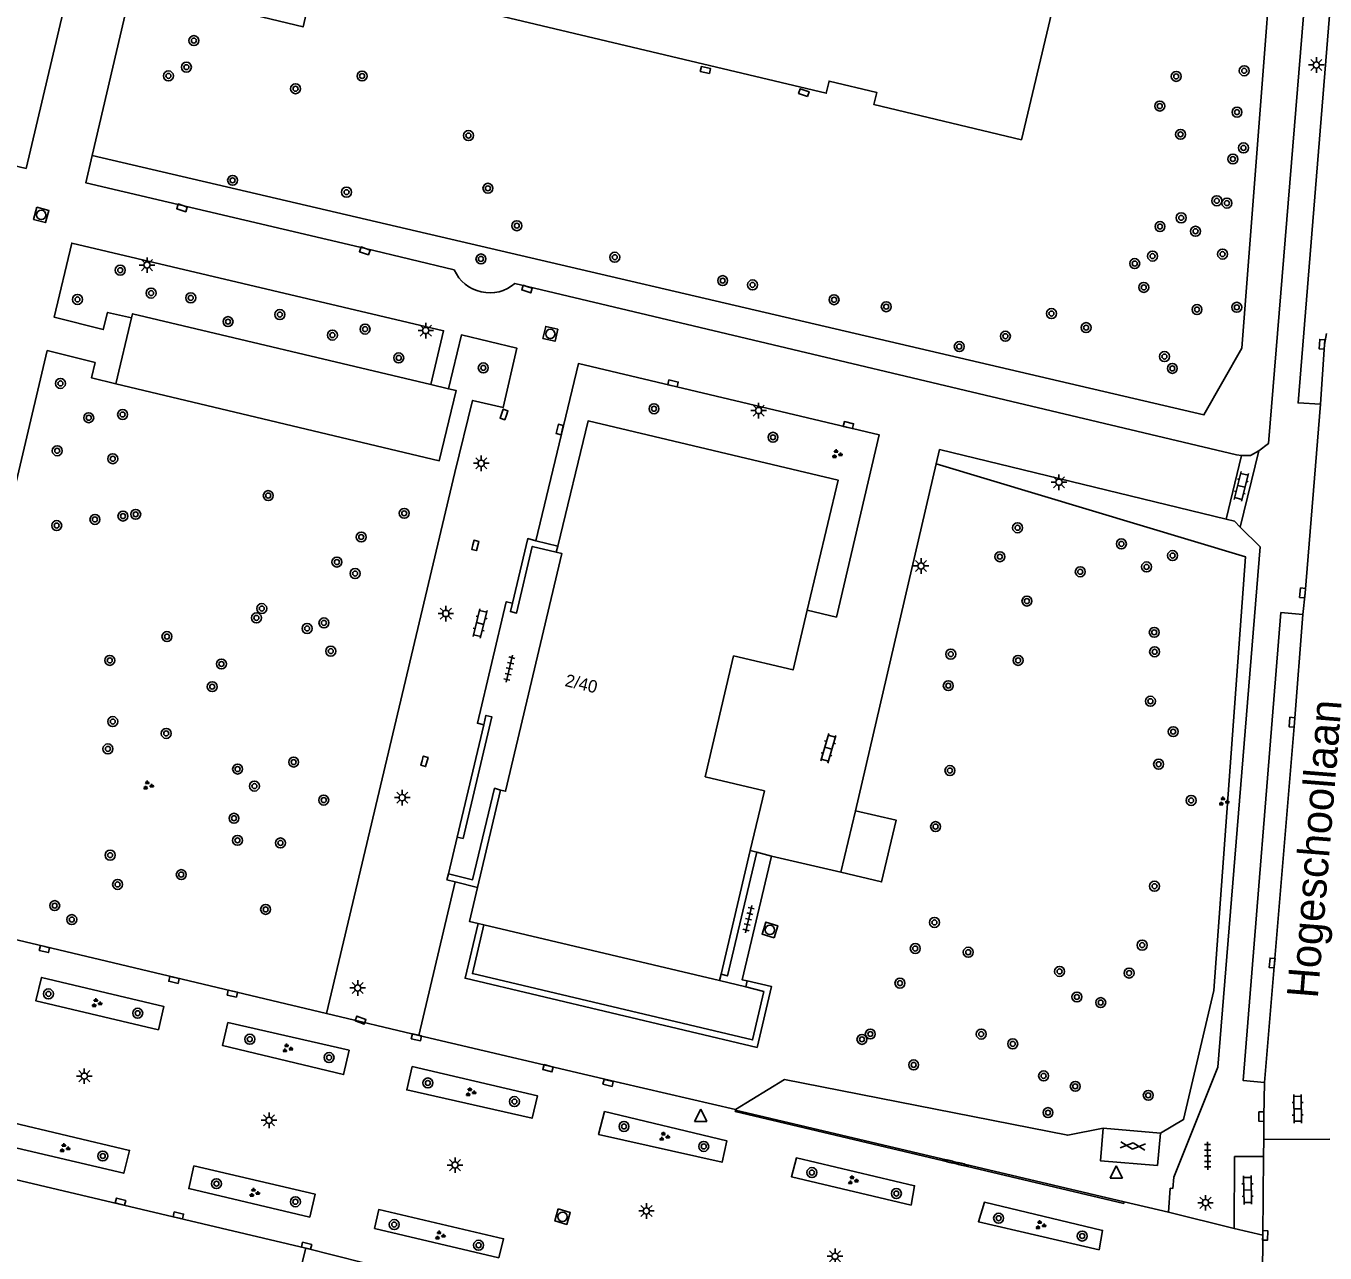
# Model space of a CAD drawing. Extents: x 131000 to 133014, y 396499 to 399001.
# Drawn here: x 131216.5 to 131320.7, y 397191 to 397289.5 of the extents above; entities that cross this region are included whole.
import ezdxf

# ---------------------------------------------------------------- set-up
doc = ezdxf.new("R2010")
doc.units = 0
for name, color, linetype in [('gg-afsc-muur', 7, 'Continuous'), ('gg-anno-huisnummerreeks BGT', 7, 'Continuous'), ('gg-anno-openbare ruimte label', 7, 'Continuous'), ('gg-bbg-bijgebouw', 7, 'Continuous'), ('gg-bbg-gedigitaliseerde bijgebouw', 7, 'Continuous'), ('gg-bbg-hoofdgebouw', 7, 'Continuous'), ('gg-knt-verharding', 7, 'Continuous'), ('gg-knt-verharding nz', 7, 'Continuous'), ('gt-grn-afwateringsgoot', 7, 'Continuous'), ('gt-grn-groengrens', 7, 'Continuous'), ('gt-grn-weggrens', 7, 'Continuous'), ('gt-symb-afwateringsgoot', 7, 'Continuous'), ('gt-symb-boom', 7, 'Continuous'), ('gt-symb-gesloten verharding', 7, 'Continuous'), ('gt-symb-groenvak', 7, 'Continuous'), ('gt-symb-klinker verharding', 7, 'Continuous'), ('gt-symb-kolk', 7, 'Continuous'), ('gt-symb-kolk center center', 7, 'Continuous'), ('gt-symb-lichtmast', 7, 'Continuous'), ('gt-symb-rioolschacht', 7, 'Continuous'), ('gt-symb-tegel verharding', 7, 'Continuous'), ('gt-symb-waterafsluiter', 7, 'Continuous')]:
    doc.layers.add(name, color=color, linetype=linetype)

# ---------------------------------------------------------------- blocks, each defined once
blk = doc.blocks.new('gt0-BOOM')
at = {"layer": 'gt-symb-boom'}
for radius in [0.4, 0.2]:
    blk.add_circle((0, 0), radius, dxfattribs=at)
blk = doc.blocks.new('gt0-KOLKCC')
at = {"layer": 'gt-symb-kolk center center'}
blk.add_lwpolyline([(-0.37, 0.2), (0.38, 0.2), (0.38, -0.2), (-0.37, -0.2)], close=True, dxfattribs=at)
blk = doc.blocks.new('gt0-LMAST')
at = {"layer": 'gt-symb-lichtmast'}
for p, q in [((-0.18, 0.17), (-0.45, 0.44)), ((-0.01, 0.25), (-0.01, 0.62)), ((0.17, 0.17), (0.44, 0.44)), ((-0.26, 0), (-0.63, 0)), ((-0.18, -0.18), (-0.45, -0.45)), ((-0.01, -0.25), (-0.01, -0.63)), ((0.44, -0.45), (0.17, -0.18)), ((0.24, 0), (0.62, 0))]:
    blk.add_line(p, q, dxfattribs=at)
blk.add_circle((-0.01, 0), 0.25, dxfattribs=at)
blk = doc.blocks.new('gt0-KOLK')
at = {"layer": 'gt-symb-kolk'}
blk.add_lwpolyline([(0, 0), (0.38, 0), (0.38, 0.4), (-0.38, 0.4), (-0.38, 0), (0, 0)], dxfattribs=at)
blk = doc.blocks.new('gt0-KL1')
at = {"layer": 'gt-symb-klinker verharding'}
for p, q in [((-1.15, 0.3), (1.15, 0.3)), ((-1, -0.3), (-1, 0.3)), ((-0.5, 0.3), (-0.5, 0.45)), ((0, -0.3), (0, 0.3)), ((0.5, 0.3), (0.5, 0.45)), ((1, -0.3), (1, 0.3)), ((-1.15, -0.3), (1.15, -0.3)), ((-0.5, -0.45), (-0.5, -0.3)), ((0.5, -0.45), (0.5, -0.3))]:
    blk.add_line(p, q, dxfattribs=at)
blk = doc.blocks.new('gt0-TEG1')
at = {"layer": 'gt-symb-tegel verharding'}
for p, q in [((-1.12, 0), (1.12, 0)), ((-0.9, -0.25), (-0.9, 0.25)), ((-0.45, -0.25), (-0.45, 0.25)), ((0, -0.25), (0, 0.25)), ((0.45, -0.25), (0.45, 0.25)), ((0.9, -0.25), (0.9, 0.25))]:
    blk.add_line(p, q, dxfattribs=at)
blk = doc.blocks.new('gt0-GRVAK')
at = {"layer": 'gt-symb-groenvak'}
for p, q in [((-0.11, 0.19), (-0.23, 0.24)), ((-0.18, 0.15), (0.09, 0.15)), ((-0.09, 0.21), (-0.16, 0.32)), ((-0.05, 0.21), (-0.05, 0.39)), ((0, 0.21), (0.06, 0.32)), ((0.02, 0.19), (0.13, 0.24)), ((0.26, -0.05), (0.2, 0.06)), ((0.3, -0.05), (0.3, 0.13)), ((0.35, -0.05), (0.41, 0.06)), ((-0.24, -0.23), (-0.36, -0.18)), ((-0.32, -0.26), (-0.05, -0.26)), ((-0.23, -0.21), (-0.29, -0.09)), ((-0.18, -0.2), (-0.18, -0.02)), ((-0.14, -0.21), (-0.07, -0.09)), ((-0.12, -0.23), (0, -0.18)), ((0.24, -0.07), (0.12, -0.02)), ((0.17, -0.11), (0.44, -0.11)), ((0.37, -0.07), (0.49, -0.02))]:
    blk.add_line(p, q, dxfattribs=at)
blk = doc.blocks.new('gt0-RS')
at = {"layer": 'gt-symb-rioolschacht'}
blk.add_lwpolyline([(-0.5, -0.5), (0.5, -0.5), (0.5, 0.5), (-0.5, 0.5)], close=True, dxfattribs=at)
blk.add_circle((0, 0), 0.375, dxfattribs=at)
blk = doc.blocks.new('gt0-GESVH1')
at = {"layer": 'gt-symb-gesloten verharding'}
for p, q in [((-0.99, -0.26), (0.01, 0.24)), ((0.01, -0.26), (-0.99, 0.24)), ((0.01, 0.24), (1.01, -0.26)), ((1.01, 0.24), (0.01, -0.26))]:
    blk.add_line(p, q, dxfattribs=at)
blk = doc.blocks.new('gt0-AFWGT_1')
at = {"layer": 'gt-symb-afwateringsgoot'}
for p, q in [((-1.08, 0), (-0.73, 0)), ((-0.23, 0), (0.22, 0)), ((0.72, 0), (1.07, 0))]:
    blk.add_line(p, q, dxfattribs=at)
for points in [[(-0.73, 0.08), (-0.23, 0.08), (-0.23, -0.08), (-0.73, -0.08)], [(0.22, 0.08), (0.72, 0.08), (0.72, -0.08), (0.22, -0.08)]]:
    blk.add_lwpolyline(points, close=True, dxfattribs=at)
blk = doc.blocks.new('gt0-WAFSL')
at = {"layer": 'gt-symb-waterafsluiter'}
for p, q in [((-0.5, -0.33), (0, 0.67)), ((0, 0.67), (0.5, -0.33)), ((0.5, -0.33), (-0.5, -0.33))]:
    blk.add_line(p, q, dxfattribs=at)

msp = doc.modelspace()

# ---------------------------------------------------------------- linework, layer by layer
at = {"layer": 'gg-afsc-muur'}
for p, q in [((131257.4, 397248.18), (131259.16, 397247.75)), ((131251.07, 397224.39), (131253.21, 397233.42)), ((131252.71, 397220.36), (131250.92, 397220.81)), ((131274.26, 397212.39), (131274.36, 397212.87))]:
    msp.add_line(p, q, dxfattribs=at)
for points in [[(131255.52, 397243.16), (131256.75, 397248.35), (131257.4, 397248.18)], [(131255.52, 397243.16), (131255.36, 397242.49), (131255.85, 397242.37), (131257.11, 397247.72), (131259.04, 397247.26)], [(131253.21, 397233.42), (131253.39, 397234.17), (131253.87, 397234.05), (131251.56, 397224.29), (131251.07, 397224.39)], [(131250.38, 397221.45), (131252.32, 397220.98), (131254.08, 397228.32), (131254.55, 397228.17)], [(131250.92, 397220.81), (131250.26, 397220.97), (131250.38, 397221.45)], [(131274.36, 397212.87), (131276.3, 397212.42), (131275.15, 397207.53), (131251.72, 397213.07), (131252.76, 397217.46)], [(131253.23, 397217.35), (131252.31, 397213.45), (131274.79, 397208.13), (131275.69, 397212.01), (131274.26, 397212.39)]]:
    msp.add_lwpolyline(points, dxfattribs=at)
at = {"layer": 'gg-bbg-bijgebouw'}
for p, q in [((131223.69, 397260.77), (131224.95, 397266.07)), ((131248.96, 397260.72), (131250.39, 397260.38))]:
    msp.add_line(p, q, dxfattribs=at)
for points in [[(131224.95, 397266.07), (131225.03, 397266.4), (131248.96, 397260.72)], [(131250.39, 397260.38), (131250.99, 397260.24), (131249.65, 397254.6), (131223.69, 397260.77)]]:
    msp.add_lwpolyline(points, dxfattribs=at)
at = {"layer": 'gg-bbg-gedigitaliseerde bijgebouw'}
msp.add_line((131283.04, 397226.52), (131281.88, 397221.58), dxfattribs=at)
msp.add_lwpolyline([(131281.88, 397221.58), (131285.15, 397220.81), (131286.32, 397225.75), (131283.04, 397226.52)], dxfattribs=at)
at = {"layer": 'gg-bbg-hoofdgebouw'}
for p, q in [((131259.16, 397247.75), (131259.04, 397247.26)), ((131254.55, 397228.17), (131252.71, 397220.36)), ((131274.61, 397223.32), (131272.27, 397213.4)), ((131252.76, 397217.46), (131253.23, 397217.35)), ((131253.23, 397217.35), (131272.14, 397212.88)), ((131272.27, 397213.4), (131272.14, 397212.88))]:
    msp.add_line(p, q, dxfattribs=at)
for points in [[(131239.74, 397293.82), (131280.7, 397284.09), (131280.93, 397285.06), (131284.76, 397284.16), (131284.52, 397283.19), (131296.37, 397280.36), (131299.28, 397292.64), (131300.25, 397292.41), (131309.51, 397331.52), (131308.54, 397331.75), (131310.56, 397340.26)], [(131279.18, 397242.61), (131281.65, 397253.05), (131261.59, 397257.79), (131259.16, 397247.75)], [(131259.04, 397247.26), (131259.47, 397247.16), (131254.97, 397228.08), (131254.55, 397228.17)], [(131279.18, 397242.61), (131278.04, 397237.82), (131273.26, 397238.94), (131270.99, 397229.24), (131275.74, 397228.11), (131274.61, 397223.32)], [(131252.71, 397220.36), (131252.06, 397217.63), (131252.76, 397217.46)]]:
    msp.add_lwpolyline(points, dxfattribs=at)
at = {"layer": 'gg-knt-verharding'}
for p, q in [((131207.38, 397218.12), (131218.18, 397263.44)), ((131289.52, 397254.36), (131289.78, 397255.51)), ((131312.79, 397249.91), (131289.78, 397255.51)), ((131312.79, 397249.91), (131314.03, 397255.03)), ((131315.41, 397255.39), (131313.93, 397249.26)), ((131240.6, 397210.25), (131250.9, 397253.65)), ((131283.04, 397226.52), (131289.52, 397254.36)), ((131250.38, 397221.45), (131251.07, 397224.39)), ((131275.13, 397223.2), (131274.61, 397223.32)), ((131275.13, 397223.2), (131276.3, 397222.88)), ((131276.3, 397222.88), (131281.88, 397221.58)), ((131248.01, 397208.49), (131250.92, 397220.81)), ((131240.6, 397210.25), (131207.38, 397218.12)), ((131272.14, 397212.88), (131274.26, 397212.39)), ((131273.43, 397202.49), (131273.43, 397202.53)), ((131307.54, 397200.65), (131302.92, 397201.04)), ((131307.3, 397198.05), (131307.54, 397200.65)), ((131315.8, 397198.78), (131315.81, 397200.14)), ((131315.81, 397200.14), (131321.11, 397200.15)), ((131315.73, 397192.47), (131315.8, 397198.78)), ((131212.81, 397197.59), (131238.94, 397191.41)), ((131308.16, 397194.31), (131308.31, 397196.23)), ((131304.61, 397195.12), (131308.16, 397194.31)), ((131313.44, 397193), (131308.16, 397194.31)), ((131254.43, 397190.63), (131244.45, 397193)), ((131238.31, 397188.97), (131238.94, 397191.41)), ((131238.94, 397191.41), (131243.58, 397190.25))]:
    msp.add_line(p, q, dxfattribs=at)
for points in [[(131143.37, 397295.53), (131153.22, 397293.21), (131172.1, 397288.66), (131216.48, 397278.05), (131227.1, 397323.04), (131154.21, 397340.33), (131143.37, 397295.53)], [(131319.61, 397297.84), (131316.19, 397255.97), (131315.41, 397255.39)], [(131320.36, 397259.14), (131318.57, 397259.24), (131321.67, 397297.63)], [(131239.74, 397293.82), (131238.72, 397289.41), (131225, 397292.72), (131224.62, 397291.22), (131221.78, 397279.09)], [(131221.78, 397279.09), (131221.27, 397276.91), (131243.73, 397271.63), (131250.85, 397269.92)], [(131248.96, 397260.72), (131249.99, 397265.03), (131220.15, 397272.07), (131218.74, 397266.11), (131222.67, 397265.13), (131223.03, 397266.5), (131224.95, 397266.07)], [(131255.71, 397268.82), (131313.64, 397255.07), (131314.03, 397255.03)], [(131250.9, 397253.65), (131252.32, 397259.44), (131254.78, 397258.88), (131255.87, 397263.64), (131251.42, 397264.69), (131250.39, 397260.38)], [(131223.69, 397260.77), (131221.73, 397261.26), (131222.02, 397262.47), (131218.18, 397263.44)], [(131279.18, 397242.61), (131281.52, 397242.05), (131284.94, 397256.68), (131260.81, 397262.4), (131257.4, 397248.18)], [(131320.36, 397259.14), (131319.13, 397243.97), (131318.95, 397242.27)], [(131314.03, 397255.03), (131314.76, 397255.02), (131315.41, 397255.39)], [(131308.31, 397196.23), (131308.51, 397196.21), (131308.59, 397197.11), (131312.12, 397205.95), (131315.52, 397247.7), (131313.93, 397249.26)], [(131313.93, 397249.26), (131313.46, 397249.75), (131312.79, 397249.91)], [(131255.52, 397243.16), (131255.02, 397243.29), (131252.71, 397233.54), (131253.21, 397233.42)], [(131315.89, 397204.71), (131314.17, 397204.86), (131317.2, 397242.41), (131318.95, 397242.27)], [(131272.27, 397213.4), (131272.77, 397213.26), (131275.13, 397223.2)], [(131276.3, 397222.88), (131273.95, 397212.96), (131274.36, 397212.87)], [(131227.11, 397208.93), (131227.55, 397210.8), (131217.73, 397213.14), (131217.26, 397211.27), (131227.11, 397208.93)], [(131232.67, 397209.53), (131232.24, 397207.68), (131241.97, 397205.35), (131242.4, 397207.3), (131232.67, 397209.53)], [(131273.43, 397202.53), (131264.19, 397204.68), (131248.01, 397208.49)], [(131247.48, 397205.98), (131247.04, 397204.11), (131257.1, 397201.84), (131257.52, 397203.65), (131247.48, 397205.98)], [(131315.89, 397204.71), (131315.83, 397201.97), (131315.81, 397200.14)], [(131262.9, 397202.37), (131262.43, 397200.54), (131272.34, 397198.31), (131272.73, 397200.02), (131262.9, 397202.37)], [(131214.89, 397201.61), (131214.41, 397199.76), (131224.32, 397197.43), (131224.79, 397199.26), (131214.89, 397201.61)], [(131302.92, 397201.04), (131302.71, 397198.43), (131307.3, 397198.05)], [(131287.51, 397194.86), (131287.79, 397196.42), (131278.31, 397198.66), (131277.91, 397197.14), (131287.51, 397194.86)], [(131313.44, 397193), (131313.48, 397198.76), (131315.8, 397198.78)], [(131229.95, 397198.03), (131229.54, 397196.2), (131239.25, 397193.91), (131239.68, 397195.75), (131229.95, 397198.03)], [(131302.62, 397191.29), (131302.88, 397192.84), (131293.4, 397195.1), (131292.91, 397193.54), (131302.62, 397191.29)], [(131254.43, 397190.63), (131254.81, 397192.17), (131244.79, 397194.51), (131244.45, 397193)], [(131315.73, 397192.47), (131315.69, 397185.77), (131315.55, 397173.32)]]:
    msp.add_lwpolyline(points, dxfattribs=at)
msp.add_arc((131253.69, 397271.18), 3.11, 204.0378, 310.6328, dxfattribs=at)
at = {"layer": 'gg-knt-verharding nz'}
msp.add_line((131315.73, 397192.47), (131313.44, 397193), dxfattribs=at)
for points in [[(131320.84, 397264.82), (131320.69, 397263.93), (131320.36, 397259.14)], [(131318.95, 397242.27), (131318.28, 397233.6), (131315.89, 397204.71)]]:
    msp.add_lwpolyline(points, dxfattribs=at)
at = {"layer": 'gt-grn-afwateringsgoot'}
msp.add_line((131304.61, 397195.12), (131273.43, 397202.49), dxfattribs=at)
msp.add_lwpolyline([(131273.43, 397202.49), (131273.4, 397202.39), (131304.58, 397195), (131304.61, 397195.12)], dxfattribs=at)
at = {"layer": 'gt-grn-groengrens'}
for points in [[(131221.78, 397279.09), (131311.01, 397258.27), (131314.07, 397263.63), (131318.09, 397316.2), (131320.17, 397338.07), (131310.56, 397340.26)], [(131307.54, 397200.65), (131309.38, 397201.73), (131311.82, 397212.1), (131314.35, 397246.9), (131289.52, 397254.36)], [(131273.43, 397202.53), (131277.34, 397204.96), (131300.08, 397200.48), (131302.92, 397201.04)]]:
    msp.add_lwpolyline(points, dxfattribs=at)
at = {"layer": 'gt-grn-weggrens'}
msp.add_line((131240.6, 397210.25), (131248.01, 397208.49), dxfattribs=at)

# ---------------------------------------------------------------- block references
at = {"layer": 'gt-symb-afwateringsgoot', "xscale": 0.9999648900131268, "yscale": 0.9999648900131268, "rotation": 166.69509315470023}
msp.add_blockref('gt0-AFWGT_1', (131291.08, 397198.26), dxfattribs=at)
at = {"layer": 'gt-symb-boom'}
for p in [(131229.95, 397288.31), (131227.91, 397285.48), (131229.35, 397286.18), (131243.45, 397285.47), (131308.79, 397285.44), (131314.25, 397285.89), (131238.11, 397284.45), (131307.47, 397283.06), (131313.67, 397282.57), (131251.99, 397280.69), (131309.14, 397280.79), (131314.19, 397279.7), (131313.34, 397278.81), (131233.06, 397277.1), (131242.2, 397276.15), (131253.55, 397276.46), (131312.05, 397275.46), (131312.86, 397275.27), (131309.19, 397274.09), (131255.87, 397273.46), (131307.49, 397273.39), (131310.34, 397273.01), (131252.99, 397270.79), (131263.73, 397270.93), (131306.89, 397271.02), (131312.51, 397271.18), (131224.04, 397269.89), (131305.46, 397270.42), (131272.39, 397269.05), (131274.79, 397268.71), (131220.61, 397267.54), (131226.52, 397268.05), (131229.7, 397267.67), (131306.19, 397268.51), (131281.33, 397267.52), (131285.52, 397266.96), (131310.46, 397266.73), (131313.65, 397266.91), (131232.69, 397265.76), (131236.85, 397266.33), (131298.78, 397266.41), (131241.07, 397264.68), (131243.69, 397265.16), (131295.08, 397264.59), (131301.56, 397265.28), (131291.38, 397263.76), (131246.39, 397262.85), (131307.85, 397262.96), (131253.18, 397262.05), (131308.48, 397262.01), (131219.24, 397260.8), (131224.23, 397258.31), (131266.88, 397258.77), (131221.51, 397258.05), (131276.43, 397256.48), (131218.98, 397255.4), (131223.44, 397254.76), (131235.92, 397251.8), (131222.01, 397249.89), (131224.26, 397250.16), (131225.28, 397250.3), (131246.83, 397250.38), (131218.94, 397249.4), (131296.06, 397249.22), (131243.38, 397248.48), (131304.39, 397247.93), (131294.64, 397246.9), (131308.5, 397246.99), (131241.43, 397246.47), (131301.09, 397245.69), (131306.41, 397246.08), (131242.89, 397245.55), (131235.4, 397242.74), (131296.81, 397243.34), (131234.97, 397241.99), (131240.39, 397241.59), (131227.79, 397240.49), (131239.04, 397241.14), (131307.03, 397240.83), (131223.2, 397238.58), (131240.94, 397239.32), (131290.7, 397239.08), (131296.1, 397238.58), (131307.06, 397239.27), (131232.16, 397238.29), (131231.42, 397236.47), (131290.5, 397236.55), (131306.72, 397235.3), (131223.44, 397233.67), (131227.73, 397232.72), (131308.55, 397232.86), (131223.05, 397231.48), (131237.96, 397230.42), (131307.38, 397230.25), (131233.46, 397229.86), (131290.63, 397229.74), (131234.81, 397228.49), (131240.37, 397227.37), (131309.99, 397227.34), (131233.17, 397225.91), (131289.48, 397225.24), (131233.45, 397224.14), (131236.9, 397223.93), (131223.23, 397222.95), (131228.94, 397221.39), (131223.83, 397220.6), (131307.05, 397220.46), (131218.78, 397218.9), (131235.71, 397218.6), (131220.15, 397217.78), (131289.39, 397217.55), (131287.85, 397215.46), (131306.06, 397215.73), (131292.1, 397215.16), (131299.43, 397213.62), (131305.01, 397213.49), (131286.62, 397212.68), (131218.28, 397211.82), (131300.82, 397211.57), (131225.44, 397210.27), (131302.73, 397211.12), (131234.44, 397208.18), (131283.57, 397208.17), (131284.24, 397208.6), (131293.14, 397208.59), (131295.67, 397207.81), (131240.8, 397206.71), (131287.72, 397206.12), (131298.15, 397205.24), (131248.73, 397204.67), (131300.69, 397204.4), (131255.68, 397203.18), (131306.55, 397203.68), (131298.5, 397202.29), (131264.47, 397201.18), (131222.64, 397198.81), (131270.87, 397199.58), (131279.55, 397197.48), (131231.76, 397196.59), (131286.33, 397195.8), (131238.1, 397195.14), (131294.54, 397193.82), (131246.03, 397193.31), (131252.8, 397191.65), (131301.25, 397192.39)]:
    msp.add_blockref('gt0-BOOM', p, dxfattribs=at)
at = {"layer": 'gt-symb-gesloten verharding', "rotation": -4.815953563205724}
msp.add_blockref('gt0-GESVH1', (131305.3, 397199.63), dxfattribs=at)
at = {"layer": 'gt-symb-groenvak'}
for p in [(131281.54, 397255.13), (131226.26, 397228.54), (131312.59, 397227.26), (131222.13, 397211.08), (131237.44, 397207.45), (131252.15, 397203.93), (131267.68, 397200.37), (131219.56, 397199.44), (131282.82, 397196.86), (131234.78, 397195.86), (131297.88, 397193.26), (131249.68, 397192.43)]:
    msp.add_blockref('gt0-GRVAK', p, dxfattribs=at)
at = {"layer": 'gt-symb-klinker verharding'}
for p, rotation in [((131314.02, 397252.54), -104.18918015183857), ((131252.92, 397241.54), -103.7721454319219), ((131280.87, 397231.53), 73.9758903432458), ((131318.54, 397202.6), 90.40106390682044), ((131314.52, 397196.08), -89.14062775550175)]:
    msp.add_blockref('gt0-KL1', p, dxfattribs=dict(at, rotation=rotation))
at = {"layer": 'gt-symb-kolk'}
for p, rotation in [((131229.06, 397275.08), 161.45633066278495), ((131243.73, 397271.63), 161.45633066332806), ((131256.75, 397268.56), 161.45633066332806), ((131320.69, 397263.93), 86.04496236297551), ((131268.36, 397260.61), -13.355340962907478), ((131255.03, 397258.25), 70.96692019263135), ((131259.51, 397257.06), 76.64465903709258), ((131282.44, 397257.27), -13.299584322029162), ((131252.34, 397247.85), -104.17514205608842), ((131319.13, 397243.97), 83.91299166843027), ((131318.28, 397233.6), 85.24111433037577), ((131248.26, 397230.53), -105.24507033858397), ((131218, 397215.61), 166.17220496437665), ((131316.69, 397214.28), 85.06501407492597), ((131228.4, 397213.14), 166.9366626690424), ((131233.08, 397212.03), 167.40904938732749), ((131243.26, 397209.53), -19.88516511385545), ((131247.86, 397208.53), 167.11702052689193), ((131258.43, 397206.04), 164.39306952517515), ((131263.24, 397204.87), 166.88085537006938), ((131315.83, 397201.97), 89.36977184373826), ((131224.01, 397194.95), -14.119602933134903), ((131228.66, 397193.85), -12.827123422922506), ((131238.95, 397191.41), -13.299584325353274), ((131315.73, 397192.44), -90.34377055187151)]:
    msp.add_blockref('gt0-KOLK', p, dxfattribs=dict(at, rotation=rotation))
at = {"layer": 'gt-symb-kolk center center'}
for p, rotation in [((131271.01, 397285.95), 167.11702052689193), ((131278.91, 397284.14), 160.78568813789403)]:
    msp.add_blockref('gt0-KOLKCC', p, dxfattribs=dict(at, rotation=rotation))
at = {"layer": 'gt-symb-lichtmast'}
for p in [(131320.05, 397286.36), (131226.2, 397270.3), (131248.57, 397265.05), (131275.28, 397258.63), (131253.02, 397254.4), (131299.39, 397252.88), (131288.32, 397246.16), (131250.18, 397242.34), (131246.68, 397227.57), (131243.11, 397212.3), (131221.16, 397205.22), (131235.99, 397201.68), (131250.92, 397198.08), (131266.28, 397194.4), (131311.15, 397195.06), (131281.42, 397190.77)]:
    msp.add_blockref('gt0-LMAST', p, dxfattribs=at)
at = {"layer": 'gt-symb-rioolschacht'}
for p, rotation in [((131217.7, 397274.32), -105.30032444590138), ((131258.56, 397264.78), -12.938810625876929), ((131276.18, 397216.95), 72.85095611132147), ((131259.54, 397193.94), -106.13420459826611)]:
    msp.add_blockref('gt0-RS', p, dxfattribs=dict(at, rotation=rotation))
at = {"layer": 'gt-symb-tegel verharding'}
for p, rotation in [((131255.27, 397237.92), 76.64465903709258), ((131274.47, 397217.82), 76.75619797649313), ((131311.31, 397198.83), -89.71352348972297)]:
    msp.add_blockref('gt0-TEG1', p, dxfattribs=dict(at, rotation=rotation))
at = {"layer": 'gt-symb-waterafsluiter'}
for p in [(131270.63, 397201.91), (131303.98, 397197.36)]:
    msp.add_blockref('gt0-WAFSL', p, dxfattribs=at)

# ---------------------------------------------------------------- texts
at = {"layer": 'gg-anno-huisnummerreeks BGT'}
msp.add_text('2/40', height=1, rotation=346.7, dxfattribs=at).set_placement((131259.67, 397236.53))
at = {"layer": 'gg-anno-openbare ruimte label'}
msp.add_text('Hogeschoollaan', height=2.5, rotation=85.4, dxfattribs=at).set_placement((131320.15, 397211.41))

doc.saveas('drawing.dxf')
